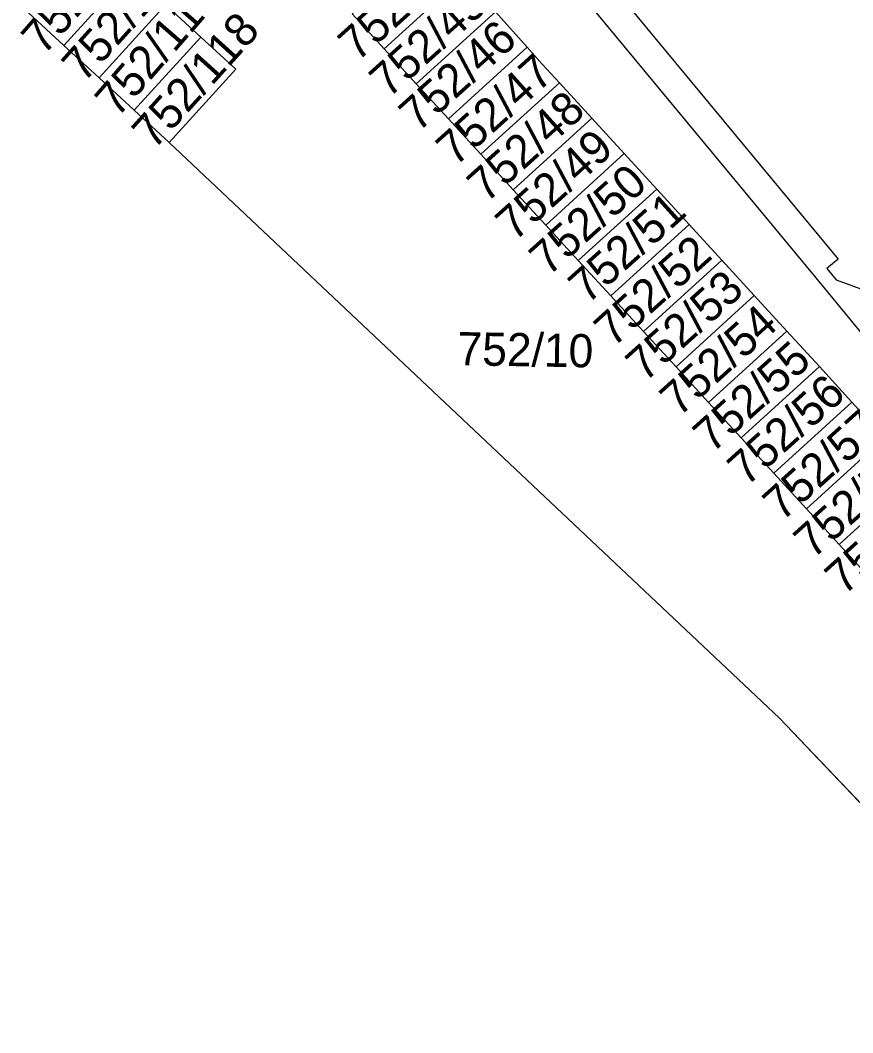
# Model space of a CAD drawing. Extents: x -263943 to -261149, y -1236934 to -1230686.
# Drawn here: x -262446.4 to -262396.2, y -1235352.2 to -1235291.2 of the extents above; entities that cross this region are included whole.
import ezdxf

# ---------------------------------------------------------------- set-up
doc = ezdxf.new("R2010")
doc.units = 0
for name, color, linetype in [('body_kn', 7, 'Continuous'), ('kladpar_druhypozemkov', 7, 'Continuous'), ('kladpar_hranice', 7, 'Continuous'), ('kladpar_parcelnecisla', 7, 'Continuous'), ('kladpar_plochy', 7, 'Continuous'), ('zappar_hrandruhpozemk', 7, 'Continuous'), ('zuob_linie', 7, 'Continuous'), ('zuob_plochy', 7, 'Continuous')]:
    doc.layers.add(name, color=color, linetype=linetype)

msp = doc.modelspace()

# ---------------------------------------------------------------- linework, layer by layer
at = {"layer": 'body_kn'}
for p, q in [((-262435.53, -1235292.18), (-262435.53, -1235292.18)), ((-262443.78, -1235292.68), (-262443.78, -1235292.68)), ((-262443.78, -1235292.68), (-262443.78, -1235292.68)), ((-262424.47, -1235292.88), (-262424.47, -1235292.88)), ((-262424.47, -1235292.88), (-262424.47, -1235292.88)), ((-262415.85, -1235292.79), (-262415.85, -1235292.79)), ((-262433.41, -1235294.11), (-262433.41, -1235294.11)), ((-262414.94, -1235293.8), (-262414.94, -1235293.8)), ((-262441.66, -1235294.64), (-262441.66, -1235294.64)), ((-262441.66, -1235294.64), (-262441.66, -1235294.64)), ((-262422.54, -1235294.99), (-262422.54, -1235294.99)), ((-262422.54, -1235294.99), (-262422.54, -1235294.99)), ((-262413.91, -1235294.93), (-262413.91, -1235294.93)), ((-262439.54, -1235296.59), (-262439.54, -1235296.59)), ((-262439.54, -1235296.59), (-262439.54, -1235296.59)), ((-262420.6, -1235297.11), (-262420.6, -1235297.11)), ((-262411.95, -1235297.07), (-262411.95, -1235297.07)), ((-262419.56, -1235298.25), (-262419.56, -1235298.25)), ((-262437.43, -1235298.53), (-262437.43, -1235298.53)), ((-262418.65, -1235299.24), (-262418.65, -1235299.24)), ((-262418.65, -1235299.24), (-262418.65, -1235299.24)), ((-262410, -1235299.2), (-262410, -1235299.2)), ((-262416.69, -1235301.38), (-262416.69, -1235301.38)), ((-262416.69, -1235301.38), (-262416.69, -1235301.38)), ((-262408.04, -1235301.34), (-262408.04, -1235301.34)), ((-262414.73, -1235303.51), (-262414.73, -1235303.51)), ((-262414.73, -1235303.51), (-262414.73, -1235303.51)), ((-262406.08, -1235303.48), (-262406.08, -1235303.48)), ((-262412.77, -1235305.64), (-262412.77, -1235305.64)), ((-262412.77, -1235305.64), (-262412.77, -1235305.64)), ((-262404.12, -1235305.62), (-262404.12, -1235305.62)), ((-262397.11, -1235305.57), (-262397.11, -1235305.57)), ((-262397.79, -1235306.12), (-262397.79, -1235306.12)), ((-262398.46, -1235306.68), (-262398.46, -1235306.68)), ((-262397.23, -1235306.8), (-262397.23, -1235306.8)), ((-262410.8, -1235307.78), (-262410.8, -1235307.78)), ((-262410.8, -1235307.78), (-262410.8, -1235307.78)), ((-262402.16, -1235307.76), (-262402.16, -1235307.76)), ((-262408.84, -1235309.92), (-262408.84, -1235309.92)), ((-262408.84, -1235309.92), (-262408.84, -1235309.92)), ((-262400.2, -1235309.9), (-262400.2, -1235309.9)), ((-262406.88, -1235312.06), (-262406.88, -1235312.06)), ((-262406.88, -1235312.06), (-262406.88, -1235312.06)), ((-262398.24, -1235312.04), (-262398.24, -1235312.04)), ((-262404.92, -1235314.2), (-262404.92, -1235314.2)), ((-262404.92, -1235314.2), (-262404.92, -1235314.2)), ((-262396.28, -1235314.18), (-262396.28, -1235314.18)), ((-262402.96, -1235316.33), (-262402.96, -1235316.33)), ((-262402.96, -1235316.33), (-262402.96, -1235316.33)), ((-262400.99, -1235318.47), (-262400.99, -1235318.47)), ((-262400.99, -1235318.47), (-262400.99, -1235318.47)), ((-262399.02, -1235320.61), (-262399.02, -1235320.61)), ((-262399.02, -1235320.61), (-262399.02, -1235320.61)), ((-262397.05, -1235322.76), (-262397.05, -1235322.76)), ((-262397.05, -1235322.76), (-262397.05, -1235322.76)), ((-262400.65, -1235333.22), (-262400.65, -1235333.22))]:
    msp.add_line(p, q, dxfattribs=at)
at = {"layer": 'kladpar_druhypozemkov'}
for p, q in [((-262439.18, -1235292.63), (-262439.18, -1235292.63)), ((-262419.15, -1235292.64), (-262419.15, -1235292.64)), ((-262436.98, -1235294.63), (-262436.98, -1235294.63)), ((-262417.3, -1235294.89), (-262417.3, -1235294.89)), ((-262415.2, -1235297.09), (-262415.2, -1235297.09)), ((-262413.45, -1235299.19), (-262413.45, -1235299.19)), ((-262411.4, -1235301.29), (-262411.4, -1235301.29)), ((-262409.25, -1235303.34), (-262409.25, -1235303.34)), ((-262407.5, -1235305.64), (-262407.5, -1235305.64)), ((-262405.5, -1235307.74), (-262405.5, -1235307.74)), ((-262415.36, -1235309.98), (-262415.36, -1235309.98)), ((-262403.55, -1235309.94), (-262403.55, -1235309.94)), ((-262401.75, -1235312.14), (-262401.75, -1235312.14)), ((-262399.75, -1235314.24), (-262399.75, -1235314.24)), ((-262397.9, -1235316.29), (-262397.9, -1235316.29))]:
    msp.add_line(p, q, dxfattribs=at)
at = {"layer": 'kladpar_hranice'}
for points in [[(-262416.72, -1235281.88), (-262397.11, -1235305.57), (-262397.79, -1235306.12), (-262397.23, -1235306.8), (-262395.58, -1235307.42)], [(-262445.91, -1235290.71), (-262441.94, -1235286.35), (-262439.8, -1235288.3), (-262443.78, -1235292.68), (-262445.91, -1235290.71)], [(-262426.4, -1235290.77), (-262421.61, -1235286.4), (-262419.69, -1235288.53), (-262424.47, -1235292.88), (-262426.4, -1235290.77)], [(-262443.78, -1235292.68), (-262439.8, -1235288.3), (-262437.66, -1235290.24), (-262441.66, -1235294.64), (-262443.78, -1235292.68)], [(-262424.47, -1235292.88), (-262419.69, -1235288.53), (-262417.77, -1235290.66), (-262422.54, -1235294.99), (-262424.47, -1235292.88)], [(-262441.66, -1235294.64), (-262437.66, -1235290.24), (-262435.53, -1235292.18), (-262439.54, -1235296.59), (-262441.66, -1235294.64)], [(-262389.55, -1235344.89), (-262400.65, -1235333.22), (-262437.43, -1235298.53), (-262433.41, -1235294.11), (-262435.53, -1235292.18), (-262437.66, -1235290.24)], [(-262445.91, -1235290.71), (-262443.78, -1235292.68), (-262441.66, -1235294.64), (-262439.54, -1235296.59), (-262437.43, -1235298.53), (-262400.65, -1235333.22), (-262389.55, -1235344.89)], [(-262426.4, -1235290.77), (-262424.47, -1235292.88), (-262422.54, -1235294.99), (-262420.6, -1235297.11), (-262419.56, -1235298.25), (-262418.65, -1235299.24), (-262416.69, -1235301.38), (-262414.73, -1235303.51)], [(-262422.54, -1235294.99), (-262417.77, -1235290.66), (-262415.85, -1235292.79), (-262420.6, -1235297.11), (-262422.54, -1235294.99)], [(-262394.32, -1235316.33), (-262396.28, -1235314.18), (-262398.24, -1235312.04), (-262400.2, -1235309.9), (-262402.16, -1235307.76), (-262404.12, -1235305.62), (-262406.08, -1235303.48), (-262408.04, -1235301.34), (-262410, -1235299.2), (-262411.95, -1235297.07), (-262413.91, -1235294.93), (-262414.94, -1235293.8), (-262415.85, -1235292.79), (-262417.77, -1235290.66)], [(-262439.54, -1235296.59), (-262435.53, -1235292.18), (-262433.41, -1235294.11), (-262437.43, -1235298.53), (-262439.54, -1235296.59)], [(-262418.65, -1235299.24), (-262419.56, -1235298.25), (-262420.6, -1235297.11), (-262415.85, -1235292.79), (-262414.94, -1235293.8), (-262413.91, -1235294.93), (-262418.65, -1235299.24)], [(-262418.65, -1235299.24), (-262413.91, -1235294.93), (-262411.95, -1235297.07), (-262416.69, -1235301.38), (-262418.65, -1235299.24)], [(-262416.69, -1235301.38), (-262411.95, -1235297.07), (-262410, -1235299.2), (-262414.73, -1235303.51), (-262416.69, -1235301.38)], [(-262414.73, -1235303.51), (-262410, -1235299.2), (-262408.04, -1235301.34), (-262412.77, -1235305.64), (-262414.73, -1235303.51)], [(-262412.77, -1235305.64), (-262408.04, -1235301.34), (-262406.08, -1235303.48), (-262410.8, -1235307.78), (-262412.77, -1235305.64)], [(-262414.73, -1235303.51), (-262412.77, -1235305.64), (-262410.8, -1235307.78), (-262408.84, -1235309.92), (-262406.88, -1235312.06), (-262404.92, -1235314.2), (-262402.96, -1235316.33), (-262400.99, -1235318.47), (-262399.02, -1235320.61), (-262397.05, -1235322.76), (-262395.07, -1235324.91)], [(-262410.8, -1235307.78), (-262406.08, -1235303.48), (-262404.12, -1235305.62), (-262408.84, -1235309.92), (-262410.8, -1235307.78)], [(-262408.84, -1235309.92), (-262404.12, -1235305.62), (-262402.16, -1235307.76), (-262406.88, -1235312.06), (-262408.84, -1235309.92)], [(-262406.88, -1235312.06), (-262402.16, -1235307.76), (-262400.2, -1235309.9), (-262404.92, -1235314.2), (-262406.88, -1235312.06)], [(-262404.92, -1235314.2), (-262400.2, -1235309.9), (-262398.24, -1235312.04), (-262402.96, -1235316.33), (-262404.92, -1235314.2)], [(-262402.96, -1235316.33), (-262398.24, -1235312.04), (-262396.28, -1235314.18), (-262400.99, -1235318.47), (-262402.96, -1235316.33)], [(-262400.99, -1235318.47), (-262396.28, -1235314.18), (-262394.32, -1235316.33), (-262399.02, -1235320.61), (-262400.99, -1235318.47)], [(-262399.02, -1235320.61), (-262394.32, -1235316.33), (-262392.35, -1235318.48), (-262397.05, -1235322.76), (-262399.02, -1235320.61)], [(-262397.05, -1235322.76), (-262392.35, -1235318.48), (-262390.38, -1235320.64), (-262395.07, -1235324.91), (-262397.05, -1235322.76)]]:
    msp.add_lwpolyline(points, dxfattribs=at)
at = {"layer": 'kladpar_plochy'}
for p, q in [((-262445.91, -1235290.71), (-262443.78, -1235292.68)), ((-262443.78, -1235292.68), (-262441.66, -1235294.64)), ((-262441.66, -1235294.64), (-262439.54, -1235296.59)), ((-262439.54, -1235296.59), (-262437.43, -1235298.53)), ((-262437.43, -1235298.53), (-262400.65, -1235333.22)), ((-262400.65, -1235333.22), (-262389.55, -1235344.89))]:
    msp.add_line(p, q, dxfattribs=at)
for points in [[(-262416.72, -1235281.88), (-262397.11, -1235305.57), (-262397.79, -1235306.12), (-262397.23, -1235306.8), (-262395.58, -1235307.42)], [(-262389.55, -1235344.89), (-262400.65, -1235333.22), (-262437.43, -1235298.53), (-262433.41, -1235294.11), (-262435.53, -1235292.18), (-262437.66, -1235290.24)], [(-262426.4, -1235290.77), (-262424.47, -1235292.88), (-262422.54, -1235294.99), (-262420.6, -1235297.11), (-262419.56, -1235298.25), (-262418.65, -1235299.24), (-262416.69, -1235301.38), (-262414.73, -1235303.51), (-262412.77, -1235305.64), (-262410.8, -1235307.78), (-262408.84, -1235309.92), (-262406.88, -1235312.06), (-262404.92, -1235314.2), (-262402.96, -1235316.33), (-262400.99, -1235318.47), (-262399.02, -1235320.61), (-262397.05, -1235322.76), (-262395.07, -1235324.91)], [(-262394.32, -1235316.33), (-262396.28, -1235314.18), (-262398.24, -1235312.04), (-262400.2, -1235309.9), (-262402.16, -1235307.76), (-262404.12, -1235305.62), (-262406.08, -1235303.48), (-262408.04, -1235301.34), (-262410, -1235299.2), (-262411.95, -1235297.07), (-262413.91, -1235294.93), (-262414.94, -1235293.8), (-262415.85, -1235292.79), (-262417.77, -1235290.66)]]:
    msp.add_lwpolyline(points, dxfattribs=at)
for points in [[(-262445.91, -1235290.71), (-262441.94, -1235286.35), (-262439.8, -1235288.3), (-262443.78, -1235292.68)], [(-262426.4, -1235290.77), (-262421.61, -1235286.4), (-262419.69, -1235288.53), (-262424.47, -1235292.88)], [(-262443.78, -1235292.68), (-262439.8, -1235288.3), (-262437.66, -1235290.24), (-262441.66, -1235294.64)], [(-262424.47, -1235292.88), (-262419.69, -1235288.53), (-262417.77, -1235290.66), (-262422.54, -1235294.99)], [(-262441.66, -1235294.64), (-262437.66, -1235290.24), (-262435.53, -1235292.18), (-262439.54, -1235296.59)], [(-262422.54, -1235294.99), (-262417.77, -1235290.66), (-262415.85, -1235292.79), (-262420.6, -1235297.11)], [(-262439.54, -1235296.59), (-262435.53, -1235292.18), (-262433.41, -1235294.11), (-262437.43, -1235298.53)], [(-262418.65, -1235299.24), (-262419.56, -1235298.25), (-262420.6, -1235297.11), (-262415.85, -1235292.79), (-262414.94, -1235293.8), (-262413.91, -1235294.93)], [(-262418.65, -1235299.24), (-262413.91, -1235294.93), (-262411.95, -1235297.07), (-262416.69, -1235301.38)], [(-262416.69, -1235301.38), (-262411.95, -1235297.07), (-262410, -1235299.2), (-262414.73, -1235303.51)], [(-262414.73, -1235303.51), (-262410, -1235299.2), (-262408.04, -1235301.34), (-262412.77, -1235305.64)], [(-262412.77, -1235305.64), (-262408.04, -1235301.34), (-262406.08, -1235303.48), (-262410.8, -1235307.78)], [(-262410.8, -1235307.78), (-262406.08, -1235303.48), (-262404.12, -1235305.62), (-262408.84, -1235309.92)], [(-262408.84, -1235309.92), (-262404.12, -1235305.62), (-262402.16, -1235307.76), (-262406.88, -1235312.06)], [(-262406.88, -1235312.06), (-262402.16, -1235307.76), (-262400.2, -1235309.9), (-262404.92, -1235314.2)], [(-262404.92, -1235314.2), (-262400.2, -1235309.9), (-262398.24, -1235312.04), (-262402.96, -1235316.33)], [(-262402.96, -1235316.33), (-262398.24, -1235312.04), (-262396.28, -1235314.18), (-262400.99, -1235318.47)], [(-262400.99, -1235318.47), (-262396.28, -1235314.18), (-262394.32, -1235316.33), (-262399.02, -1235320.61)], [(-262399.02, -1235320.61), (-262394.32, -1235316.33), (-262392.35, -1235318.48), (-262397.05, -1235322.76)], [(-262397.05, -1235322.76), (-262392.35, -1235318.48), (-262390.38, -1235320.64), (-262395.07, -1235324.91)]]:
    msp.add_lwpolyline(points, close=True, dxfattribs=at)
at = {"layer": 'zappar_hrandruhpozemk'}
msp.add_line((-262419.61, -1235281.14), (-262398.46, -1235306.68), dxfattribs=at)
msp.add_lwpolyline([(-262398.46, -1235306.68), (-262363.38, -1235349.34), (-262355.4, -1235359.15)], dxfattribs=at)
at = {"layer": 'zuob_linie'}
msp.add_lwpolyline([(-262416.72, -1235281.88), (-262397.11, -1235305.57), (-262397.79, -1235306.12), (-262397.23, -1235306.8), (-262395.58, -1235307.42)], dxfattribs=at)
at = {"layer": 'zuob_plochy'}
msp.add_lwpolyline([(-262416.72, -1235281.88), (-262397.11, -1235305.57), (-262397.79, -1235306.12), (-262397.23, -1235306.8), (-262395.58, -1235307.42)], dxfattribs=at)

# ---------------------------------------------------------------- texts
at = {"layer": 'kladpar_parcelnecisla'}
for s, rotation, p in [('752/115', 49, (-262444.99, -1235293.333)), ('752/116', 48, (-262442.58, -1235294.988)), ('752/44', 42, (-262426.095, -1235293.712)), ('752/117', 49, (-262440.553, -1235297.096)), ('752/45', 42, (-262424.216, -1235295.909)), ('752/118', 48, (-262438.346, -1235299.025)), ('752/46', 42, (-262422.435, -1235297.962)), ('752/47', 42, (-262420.19, -1235300.03)), ('752/48', 42, (-262418.323, -1235302.227)), ('752/49', 42, (-262416.615, -1235304.542)), ('752/50', 42, (-262414.58, -1235306.64)), ('752/51', 42, (-262412.222, -1235308.325)), ('752/52', 42, (-262410.671, -1235310.927)), ('752/53', 42, (-262408.762, -1235313.027)), ('752/54', 42, (-262406.706, -1235315.119)), ('752/10', 359, (-262420.063, -1235311.95)), ('752/55', 42, (-262404.707, -1235317.305)), ('752/56', 42, (-262402.636, -1235319.309)), ('752/57', 42, (-262400.501, -1235321.427)), ('752/58', 42, (-262398.634, -1235323.684)), ('752/59', 42, (-262396.756, -1235325.879))]:
    msp.add_text(s, height=2, rotation=rotation, dxfattribs=at).set_placement(p)

doc.saveas('drawing.dxf')
